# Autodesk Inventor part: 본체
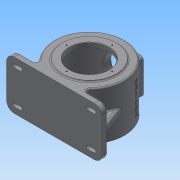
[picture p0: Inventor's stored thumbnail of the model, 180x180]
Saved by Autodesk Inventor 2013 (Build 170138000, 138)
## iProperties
Created: 2015-06
Part Number: 본체
Material: 일반
Document SubType Name: Modeling
Designer: Administrator
Density: 1 g/cm^3
Author: Administrator
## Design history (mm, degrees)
sketch "스케치1"
  geometry: C1 r 85 at (0, 0); 1 further point
  constraints: 1 centre point, 1 coincident
  dimensions: "d0" = 170 diameter of C1
extrude "돌출1" new body sketch "스케치1" stored distance "d1" = 118; taper "d2" = 0 deg
sketch "스케치2"
  geometry: L1 (-115, -71)-(115, -71); L2 (115, -71)-(115, -85); L3 (115, -85)-(-115, -85); L4 (-115, -85)-(-115, -71); 3 further points
  constraints: 8 end point, 2 parallel, 2 vertical alignment, 1 horizontal, 1 midpoint, 1 perpendicular, 1 other
  dimensions: "d3" = 230 distance of L2.end L3.end; "d5" = 14 distance of L1.end L2.end
extrude "돌출2" join sketch "스케치2" stored distance "d6" = 118; taper "d7" = 0 deg
sketch "스케치3"
  geometry: C1 r 65 at (0, 0); A1 r 85 centre (0, 0) between (46.733, -71) and (-46.733, -71) reference
  constraints: 1 centre point, 1 coincident
  dimensions: "d8" = 130 diameter of C1
extrude "돌출3" join sketch "스케치3" distance "d9" = 3; taper "d10" = 0 deg
sketch "스케치4"
  geometry: C1 r 65 at (0, 0); A1 r 85 centre (0, 0) between (46.733, -71) and (-46.733, -71) reference
  constraints: 1 centre point, 1 coincident
  dimensions: "d11" = 130 diameter of C1
extrude "돌출4" join sketch "스케치4" distance "d12" = 13; taper "d13" = 0 deg
hole "구멍1" diameter "d16" = 95; stored, may be unused: countersink angle "d20" = 90 deg, drill point angle "d22" = 0 deg; dims "d14" = 10, "d15" = 10, "d17" = 6, "d18" = 4, "d19" = 2, "d21" = 11
sketch "스케치5"
  geometry: C1 r 47.5 at (0, 0) reference; C2 r 77 at (0, 0)
  constraints: 1 centre point, 1 coincident
  dimensions: "d23" = 154 diameter of C2
extrude "돌출5" cut sketch "스케치5" distance "d24" = 102; taper "d25" = 0 deg
sketch "스케치6"
  geometry: C1 r 77 at (0, 0) reference; C2 r 31 at (0, 0)
  constraints: 1 centre point, 1 coincident
  dimensions: "d26" = 62 diameter of C2
extrude "돌출6" join sketch "스케치6" distance "d27" = 3.5; taper "d28" = -25 deg
node "작업 평면1"
sketch "스케치8"
  geometry: L1 (-157.5, -16.5)-(-72.5, -16.5); L2 (-72.5, -16.5)-(-72.5, -101.5); L3 (-72.5, -101.5)-(-157.5, -101.5); L4 (-157.5, -101.5)-(-157.5, -16.5); L5 (-157.5, -16.5)-(-72.5, -101.5); L6 (-72.5, -16.5)-(-157.5, -101.5); 1 further point
  constraints: 12 end point, 2 midpoint, 2 parallel, 1 horizontal, 1 perpendicular
  dimensions: "d30" = 85 distance of L2.end L3.end; "d31" = 85 distance of L1.end L2.end
extrude "돌출7" join sketch "스케치8" stored distance "d32" = 3.5; taper "d33" = 0 deg
fillet "모깎기1" dims "d34" = 7, "d35" = 18
sketch "스케치9"
  geometry: C1 r 35 at (115, 59); 1 further point
  constraints: 1 centre point, 1 coincident
  dimensions: "d36" = 70 diameter of C1
extrude "돌출8" cut sketch "스케치9" stored distance "d37" = 3.5; taper "d38" = 0 deg
sketch "스케치10"
  geometry: C1 r 29.368 at (0, 0) reference; 1 further point
  constraints: 1 coincident
hole "구멍2" sketch "스케치10" at (0, 0) diameter "d39" = 30; stored, may be unused: countersink angle "d43" = 90 deg, drill point angle "d45" = 0 deg; dims "d40" = 6, "d41" = 47, "d42" = 14, "d44" = 17
fillet "모깎기2" dims "d46" = 0.3, "d47" = 3
chamfer "모따기1" distance "d48" = 1; stored, may be unused: second distance "d49" = 2, angle "d50" = 45 deg
sketch "스케치11"
  geometry: A1 r 7 centre (79.5, 23.5) between (72.5, 23.5) and (79.5, 16.5) reference; A2 r 7 centre (150.5, 23.5) between (150.5, 16.5) and (157.5, 23.5) reference; A3 r 7 centre (150.5, 94.5) between (157.5, 94.5) and (150.5, 101.5) reference; A4 r 7 centre (79.5, 94.5) between (79.5, 101.5) and (72.5, 94.5) reference; 4 further points
  constraints: 4 coincident
hole "구멍3" sketch "스케치11" at (79.5, 94.5), (150.5, 94.5), (79.5, 23.5), (150.5, 23.5) diameter "d51" = 3.242; stored, may be unused: countersink angle "d55" = 90 deg, drill point angle "d57" = 118 deg; dims "d52" = 10, "d53" = 47, "d54" = 14, "d56" = 13
sketch "스케치12"
  geometry: C1 r 65 at (0, 0) reference; 1 further point
  constraints: 1 vertical alignment
  dimensions: "d58" = 55 distance of point (0, 55) C1.centre
hole "구멍4" sketch "스케치12" at (0, 55) diameter "d59" = 3.242; stored, may be unused: countersink angle "d63" = 90 deg, drill point angle "d65" = 0 deg; dims "d60" = 10, "d61" = 47, "d62" = 14, "d64" = 13
sketch "스케치14"
  geometry: L1 (46.733, -71)-(115, -71) reference; L2 (115, -71)-(115, -85) reference; L3 (115, -85)-(-115, -85) reference; L4 (-115, -85)-(-115, -71) reference; L5 (-115, -71)-(-46.733, -71) reference; L6 (-42.5, 73.612)-(-42.5, 88) reference; L7 (-42.5, 88)-(-36, 88) reference; L8 (-36, 88)-(-35, 87) reference; L9 (-35, 87)-(-35, 68.586) reference; L10 (35, 68.586)-(35, 87) reference; L11 (35, 87)-(36, 88) reference; L12 (36, 88)-(42.5, 88) reference; L13 (42.5, 88)-(42.5, 73.612) reference; L14 (-109, -71)-(-84.87, -4.703); A1 r 85 centre (0, 0) between (-42.5, 73.612) and (-46.733, -71) reference; A2 r 77 centre (0, 0) between (-35, 68.586) and (35, 68.586) reference; A3 r 85 centre (0, 0) between (46.733, -71) and (42.5, 73.612) reference; 1 further point
  constraints: 2 end point, 1 point on circle, 1 point on line
  dimensions: "d69" = 6 distance from line of L14.start L4; "d70" = 110 deg angle of L14 L5
feature "리브1" sketch "스케치14" dims "d71" = 1, "d72" = 15, "d73" = 0, "d74" = 0, "d75" = 1, "d76" = 1
sketch "스케치15"
  geometry: L1 (0, 118)-(50.267, 118) reference; L2 (0, 109)-(16, 109); L3 (0, 91)-(16, 91); A1 r 18 centre (0, 100) between (0, 118) and (-18, 100) reference; A2 r 9 centre (0, 100) between (0, 109) and (0, 91); A3 r 9 centre (16, 100) between (16, 91) and (16, 109); 1 further point
  constraints: 4 end point, 4 point on circle, 2 centre point, 2 parallel, 2 tangent, 1 horizontal alignment
  dimensions: "d77" = 18 diameter of A2; "d79" = 18 diameter of A3; "d80" = 97 horizontal distance of A2.centre point (97, 59); "d82" = 18 distance from line of A2.centre L1; "d83" = 16 distance of A3.centre A1.centre
extrude "돌출9" join sketch "스케치15" distance "d84" = 3; taper "d85" = 0 deg
sketch "스케치16"
  geometry: L1 (16, 109)-(0, 109) reference; L2 (0, 91)-(16, 91) reference; L3 (0, 104)-(16, 104); L4 (16, 96)-(0, 96); A1 r 9 centre (0, 100) between (0, 109) and (0, 91) reference; A2 r 9 centre (16, 100) between (16, 91) and (16, 109) reference; A3 r 4 centre (16, 100) between (16, 96) and (16, 104); A4 r 4 centre (0, 100) between (0, 104) and (0, 96); 1 further point
  constraints: 4 end point, 4 point on circle, 2 centre point, 3 other
  dimensions: "d86" = 8 distance between parallel lines of L4 L3
extrude "돌출10" cut sketch "스케치16" stored distance "d88" = 3; taper "d89" = 0 deg
node "작업 평면4"
  node "작업 평면3"
sketch "스케치17"
  geometry: L1 (-84.098, -59)-(85, -59) reference; 3 further points
  constraints: 1 coincident, 1 other
feature "엠보싱1" sketch "스케치17" dims "d92" = 0.5, "d93" = 0
fillet "모깎기3" dims "d94" = 7.5
fillet "모깎기6" dims "d97" = 3
fillet "모깎기7" dims "d98" = 3
fillet "모깎기9" dims "d100" = 3
fillet "모깎기10" dims "d101" = 3
node "솔리드1"
pattern_circular "원형 패턴1" dims angle "d67" = 360 deg
mirror "대칭1"
mirror "대칭2"
mirror "대칭3"
node "작업 평면2"
node "절단 모서리 투영1"
other parameters: "d29" = -173, "d90" = 25 deg
